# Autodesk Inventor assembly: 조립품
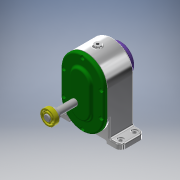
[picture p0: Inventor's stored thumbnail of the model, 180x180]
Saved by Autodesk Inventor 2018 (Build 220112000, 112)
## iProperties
Created: 2021-05
Part Number: 조립품
Material: 일반
Document SubType Name: Assembly
Designer: admin
Author: admin
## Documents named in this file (14)
- C:\Users\admin\Desktop\710509V1003\조립품.iam
- C:\Users\admin\Desktop\710509V1003\부품.ipt
- C:\Users\admin\Desktop\710509V1003\710509V1003\베어링 6001.ipt
- 베어링 6001.ipt
- C:\Users\admin\Desktop\710509V1003\710509V1003\축 A.ipt
- C:\Users\admin\Desktop\710509V1003\710509V1003\축 B.ipt
- C:\Users\admin\Desktop\710509V1003\710509V1003\칼라.ipt
- C:\Users\admin\Desktop\710509V1003\710509V1003\커버 B.ipt
- C:\Users\admin\Desktop\710509V1003\710509V1003\개스킷 B.ipt
- C:\Users\admin\Desktop\710509V1003\710509V1003\오일 실 12 22 7.ipt
- C:\Users\admin\Desktop\710509V1003\710509V1003\베어링 6002.ipt
- 베어링 6002.ipt
- C:\Users\admin\Desktop\710509V1003\710509V1003\개스킷 A.ipt
- C:\Users\admin\Desktop\710509V1003\710509V1003\커버 A.ipt
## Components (2 placed, 2 different names)
1. 개스킷 B:1
2. 개스킷 A:1
